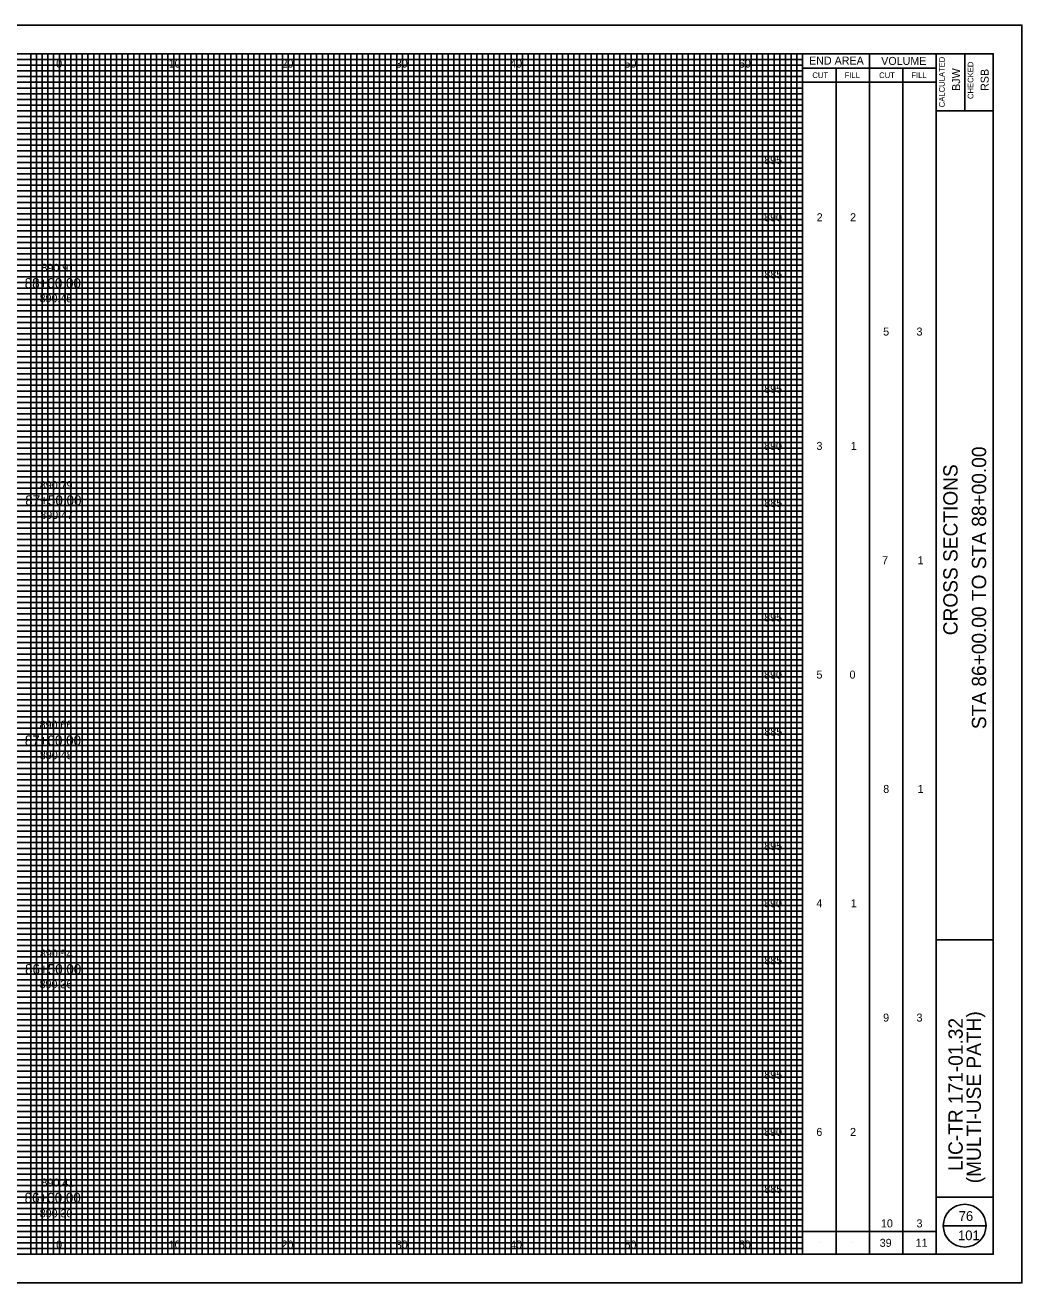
# Model space of a CAD drawing. Extents: x -10 to 160, y -2 to 3672.
# Drawn here: x 72.8 to 160, y 802.5 to 912.5 of the extents above; entities that cross this region are included whole.
import ezdxf

# ---------------------------------------------------------------- set-up
doc = ezdxf.new("R2010")
doc.units = 0
for name, color, linetype in [('SH_Border', 7, 'Continuous'), ('SH_Cut_Line', 7, 'Continuous'), ('SH_Data', 7, 'Continuous'), ('SH_Major_Grid_Line', 7, 'Continuous'), ('SH_Minor_Grid_Line', 7, 'Continuous'), ('SH_Text', 7, 'Continuous'), ('TX_P_10', 7, 'Continuous'), ('TX_X_10', 7, 'Continuous')]:
    doc.layers.add(name, color=color, linetype=linetype)

msp = doc.modelspace()

# ---------------------------------------------------------------- linework, layer by layer
at = {"layer": 'SH_Border'}
for p, q in [((152.5, 805), (152.5, 910)), ((155, 910), (155, 905)), ((152.5, 905), (157.5, 905)), ((152.5, 832.5), (157.5, 832.5)), ((152.5, 810), (157.5, 810))]:
    msp.add_line(p, q, dxfattribs=at)
msp.add_lwpolyline([(0, 910), (157.5, 910), (157.5, 805), (0, 805)], close=True, dxfattribs=at)
at = {"layer": 'SH_Cut_Line'}
msp.add_lwpolyline([(-10, 802.5), (160, 802.5), (160, 912.5), (-10, 912.5)], close=True, dxfattribs=at)
at = {"layer": 'SH_Data'}
for p, q in [((140.83, 805), (140.83, 910)), ((146.67, 805), (146.67, 910)), ((140.83, 908.75), (152.5, 908.75)), ((143.75, 805), (143.75, 908.75)), ((149.58, 805), (149.58, 908.75)), ((140.83, 907.5), (152.5, 907.5)), ((153.12, 807.5), (156.88, 807.5)), ((140.83, 807), (152.5, 807)), ((142.29, 806), (142.29, 806)), ((145.21, 806), (145.21, 806)), ((148.12, 806), (148.12, 806)), ((151.04, 806), (151.04, 806))]:
    msp.add_line(p, q, dxfattribs=at)
msp.add_circle((155, 807.5), 1.87, dxfattribs=at)
at = {"layer": 'SH_Major_Grid_Line'}
for p, q in [((75.83, 805), (75.83, 910)), ((80.83, 805), (80.83, 910)), ((85.83, 805), (85.83, 910)), ((90.83, 805), (90.83, 910)), ((95.83, 805), (95.83, 910)), ((100.83, 805), (100.83, 910)), ((105.83, 805), (105.83, 910)), ((110.83, 805), (110.83, 910)), ((115.83, 805), (115.83, 910)), ((120.83, 805), (120.83, 910)), ((125.83, 805), (125.83, 910)), ((130.83, 805), (130.83, 910)), ((135.83, 805), (135.83, 910)), ((5.83, 905), (140.83, 905)), ((5.83, 900), (140.83, 900)), ((5.83, 895), (140.83, 895)), ((5.83, 890), (140.83, 890)), ((5.83, 885), (140.83, 885)), ((5.83, 880), (140.83, 880)), ((5.83, 875), (140.83, 875)), ((5.83, 870), (140.83, 870)), ((5.83, 865), (140.83, 865)), ((5.83, 860), (140.83, 860)), ((5.83, 855), (140.83, 855)), ((5.83, 850), (140.83, 850)), ((5.83, 845), (140.83, 845)), ((5.83, 840), (140.83, 840)), ((5.83, 835), (140.83, 835)), ((5.83, 830), (140.83, 830)), ((5.83, 825), (140.83, 825)), ((5.83, 820), (140.83, 820)), ((5.83, 815), (140.83, 815)), ((5.83, 810), (140.83, 810))]:
    msp.add_line(p, q, dxfattribs=at)
at = {"layer": 'SH_Minor_Grid_Line'}
for p, q in [((73.33, 805), (73.33, 910)), ((73.83, 805), (73.83, 910)), ((74.33, 805), (74.33, 910)), ((74.83, 805), (74.83, 910)), ((75.33, 805), (75.33, 910)), ((76.33, 805), (76.33, 910)), ((76.83, 805), (76.83, 910)), ((77.33, 805), (77.33, 910)), ((77.83, 805), (77.83, 910)), ((78.33, 805), (78.33, 910)), ((78.83, 805), (78.83, 910)), ((79.33, 805), (79.33, 910)), ((79.83, 805), (79.83, 910)), ((80.33, 805), (80.33, 910)), ((81.33, 805), (81.33, 910)), ((81.83, 805), (81.83, 910)), ((82.33, 805), (82.33, 910)), ((82.83, 805), (82.83, 910)), ((83.33, 805), (83.33, 910)), ((83.83, 805), (83.83, 910)), ((84.33, 805), (84.33, 910)), ((84.83, 805), (84.83, 910)), ((85.33, 805), (85.33, 910)), ((86.33, 805), (86.33, 910)), ((86.83, 805), (86.83, 910)), ((87.33, 805), (87.33, 910)), ((87.83, 805), (87.83, 910)), ((88.33, 805), (88.33, 910)), ((88.83, 805), (88.83, 910)), ((89.33, 805), (89.33, 910)), ((89.83, 805), (89.83, 910)), ((90.33, 805), (90.33, 910)), ((91.33, 805), (91.33, 910)), ((91.83, 805), (91.83, 910)), ((92.33, 805), (92.33, 910)), ((92.83, 805), (92.83, 910)), ((93.33, 805), (93.33, 910)), ((93.83, 805), (93.83, 910)), ((94.33, 805), (94.33, 910)), ((94.83, 805), (94.83, 910)), ((95.33, 805), (95.33, 910)), ((96.33, 805), (96.33, 910)), ((96.83, 805), (96.83, 910)), ((97.33, 805), (97.33, 910)), ((97.83, 805), (97.83, 910)), ((98.33, 805), (98.33, 910)), ((98.83, 805), (98.83, 910)), ((99.33, 805), (99.33, 910)), ((99.83, 805), (99.83, 910)), ((100.33, 805), (100.33, 910)), ((101.33, 805), (101.33, 910)), ((101.83, 805), (101.83, 910)), ((102.33, 805), (102.33, 910)), ((102.83, 805), (102.83, 910)), ((103.33, 805), (103.33, 910)), ((103.83, 805), (103.83, 910)), ((104.33, 805), (104.33, 910)), ((104.83, 805), (104.83, 910)), ((105.33, 805), (105.33, 910)), ((106.33, 805), (106.33, 910)), ((106.83, 805), (106.83, 910)), ((107.33, 805), (107.33, 910)), ((107.83, 805), (107.83, 910)), ((108.33, 805), (108.33, 910)), ((108.83, 805), (108.83, 910)), ((109.33, 805), (109.33, 910)), ((109.83, 805), (109.83, 910)), ((110.33, 805), (110.33, 910)), ((111.33, 805), (111.33, 910)), ((111.83, 805), (111.83, 910)), ((112.33, 805), (112.33, 910)), ((112.83, 805), (112.83, 910)), ((113.33, 805), (113.33, 910)), ((113.83, 805), (113.83, 910)), ((114.33, 805), (114.33, 910)), ((114.83, 805), (114.83, 910)), ((115.33, 805), (115.33, 910)), ((116.33, 805), (116.33, 910)), ((116.83, 805), (116.83, 910)), ((117.33, 805), (117.33, 910)), ((117.83, 805), (117.83, 910)), ((118.33, 805), (118.33, 910)), ((118.83, 805), (118.83, 910)), ((119.33, 805), (119.33, 910)), ((119.83, 805), (119.83, 910)), ((120.33, 805), (120.33, 910)), ((121.33, 805), (121.33, 910)), ((121.83, 805), (121.83, 910)), ((122.33, 805), (122.33, 910)), ((122.83, 805), (122.83, 910)), ((123.33, 805), (123.33, 910)), ((123.83, 805), (123.83, 910)), ((124.33, 805), (124.33, 910)), ((124.83, 805), (124.83, 910)), ((125.33, 805), (125.33, 910)), ((126.33, 805), (126.33, 910)), ((126.83, 805), (126.83, 910)), ((127.33, 805), (127.33, 910)), ((127.83, 805), (127.83, 910)), ((128.33, 805), (128.33, 910)), ((128.83, 805), (128.83, 910)), ((129.33, 805), (129.33, 910)), ((129.83, 805), (129.83, 910)), ((130.33, 805), (130.33, 910)), ((131.33, 805), (131.33, 910)), ((131.83, 805), (131.83, 910)), ((132.33, 805), (132.33, 910)), ((132.83, 805), (132.83, 910)), ((133.33, 805), (133.33, 910)), ((133.83, 805), (133.83, 910)), ((134.33, 805), (134.33, 910)), ((134.83, 805), (134.83, 910)), ((135.33, 805), (135.33, 910)), ((136.33, 805), (136.33, 910)), ((136.83, 805), (136.83, 910)), ((137.33, 805), (137.33, 910)), ((137.83, 805), (137.83, 910)), ((138.33, 805), (138.33, 910)), ((138.83, 805), (138.83, 910)), ((139.33, 805), (139.33, 910)), ((139.83, 805), (139.83, 910)), ((140.33, 805), (140.33, 910)), ((5.83, 909.5), (140.83, 909.5)), ((5.83, 909), (140.83, 909)), ((5.83, 908.5), (140.83, 908.5)), ((5.83, 908), (140.83, 908)), ((5.83, 907.5), (140.83, 907.5)), ((5.83, 907), (140.83, 907)), ((5.83, 906.5), (140.83, 906.5)), ((5.83, 906), (140.83, 906)), ((5.83, 905.5), (140.83, 905.5)), ((5.83, 904.5), (140.83, 904.5)), ((5.83, 904), (140.83, 904)), ((5.83, 903.5), (140.83, 903.5)), ((5.83, 903), (140.83, 903)), ((5.83, 902.5), (140.83, 902.5)), ((5.83, 902), (140.83, 902)), ((5.83, 901.5), (140.83, 901.5)), ((5.83, 901), (140.83, 901)), ((5.83, 900.5), (140.83, 900.5)), ((5.83, 899.5), (140.83, 899.5)), ((5.83, 899), (140.83, 899)), ((5.83, 898.5), (140.83, 898.5)), ((5.83, 898), (140.83, 898)), ((5.83, 897.5), (140.83, 897.5)), ((5.83, 897), (140.83, 897)), ((5.83, 896.5), (140.83, 896.5)), ((5.83, 896), (140.83, 896)), ((5.83, 895.5), (140.83, 895.5)), ((5.83, 894.5), (140.83, 894.5)), ((5.83, 894), (140.83, 894)), ((5.83, 893.5), (140.83, 893.5)), ((5.83, 893), (140.83, 893)), ((5.83, 892.5), (140.83, 892.5)), ((5.83, 892), (140.83, 892)), ((5.83, 891.5), (140.83, 891.5)), ((5.83, 891), (140.83, 891)), ((5.83, 890.5), (140.83, 890.5)), ((5.83, 889.5), (140.83, 889.5)), ((5.83, 889), (140.83, 889)), ((5.83, 888.5), (140.83, 888.5)), ((5.83, 888), (140.83, 888)), ((5.83, 887.5), (140.83, 887.5)), ((5.83, 887), (140.83, 887)), ((5.83, 886.5), (140.83, 886.5)), ((5.83, 886), (140.83, 886)), ((5.83, 885.5), (140.83, 885.5)), ((5.83, 884.5), (140.83, 884.5)), ((5.83, 884), (140.83, 884)), ((5.83, 883.5), (140.83, 883.5)), ((5.83, 883), (140.83, 883)), ((5.83, 882.5), (140.83, 882.5)), ((5.83, 882), (140.83, 882)), ((5.83, 881.5), (140.83, 881.5)), ((5.83, 881), (140.83, 881)), ((5.83, 880.5), (140.83, 880.5)), ((5.83, 879.5), (140.83, 879.5)), ((5.83, 879), (140.83, 879)), ((5.83, 878.5), (140.83, 878.5)), ((5.83, 878), (140.83, 878)), ((5.83, 877.5), (140.83, 877.5)), ((5.83, 877), (140.83, 877)), ((5.83, 876.5), (140.83, 876.5)), ((5.83, 876), (140.83, 876)), ((5.83, 875.5), (140.83, 875.5)), ((5.83, 874.5), (140.83, 874.5)), ((5.83, 874), (140.83, 874)), ((5.83, 873.5), (140.83, 873.5)), ((5.83, 873), (140.83, 873)), ((5.83, 872.5), (140.83, 872.5)), ((5.83, 872), (140.83, 872)), ((5.83, 871.5), (140.83, 871.5)), ((5.83, 871), (140.83, 871)), ((5.83, 870.5), (140.83, 870.5)), ((5.83, 869.5), (140.83, 869.5)), ((5.83, 869), (140.83, 869)), ((5.83, 868.5), (140.83, 868.5)), ((5.83, 868), (140.83, 868)), ((5.83, 867.5), (140.83, 867.5)), ((5.83, 867), (140.83, 867)), ((5.83, 866.5), (140.83, 866.5)), ((5.83, 866), (140.83, 866)), ((5.83, 865.5), (140.83, 865.5)), ((5.83, 864.5), (140.83, 864.5)), ((5.83, 864), (140.83, 864)), ((5.83, 863.5), (140.83, 863.5)), ((5.83, 863), (140.83, 863)), ((5.83, 862.5), (140.83, 862.5)), ((5.83, 862), (140.83, 862)), ((5.83, 861.5), (140.83, 861.5)), ((5.83, 861), (140.83, 861)), ((5.83, 860.5), (140.83, 860.5)), ((5.83, 859.5), (140.83, 859.5)), ((5.83, 859), (140.83, 859)), ((5.83, 858.5), (140.83, 858.5)), ((5.83, 858), (140.83, 858)), ((5.83, 857.5), (140.83, 857.5)), ((5.83, 857), (140.83, 857)), ((5.83, 856.5), (140.83, 856.5)), ((5.83, 856), (140.83, 856)), ((5.83, 855.5), (140.83, 855.5)), ((5.83, 854.5), (140.83, 854.5)), ((5.83, 854), (140.83, 854)), ((5.83, 853.5), (140.83, 853.5)), ((5.83, 853), (140.83, 853)), ((5.83, 852.5), (140.83, 852.5)), ((5.83, 852), (140.83, 852)), ((5.83, 851.5), (140.83, 851.5)), ((5.83, 851), (140.83, 851)), ((5.83, 850.5), (140.83, 850.5)), ((5.83, 849.5), (140.83, 849.5)), ((5.83, 849), (140.83, 849)), ((5.83, 848.5), (140.83, 848.5)), ((5.83, 848), (140.83, 848)), ((5.83, 847.5), (140.83, 847.5)), ((5.83, 847), (140.83, 847)), ((5.83, 846.5), (140.83, 846.5)), ((5.83, 846), (140.83, 846)), ((5.83, 845.5), (140.83, 845.5)), ((5.83, 844.5), (140.83, 844.5)), ((5.83, 844), (140.83, 844)), ((5.83, 843.5), (140.83, 843.5)), ((5.83, 843), (140.83, 843)), ((5.83, 842.5), (140.83, 842.5)), ((5.83, 842), (140.83, 842)), ((5.83, 841.5), (140.83, 841.5)), ((5.83, 841), (140.83, 841)), ((5.83, 840.5), (140.83, 840.5)), ((5.83, 839.5), (140.83, 839.5)), ((5.83, 839), (140.83, 839)), ((5.83, 838.5), (140.83, 838.5)), ((5.83, 838), (140.83, 838)), ((5.83, 837.5), (140.83, 837.5)), ((5.83, 837), (140.83, 837)), ((5.83, 836.5), (140.83, 836.5)), ((5.83, 836), (140.83, 836)), ((5.83, 835.5), (140.83, 835.5)), ((5.83, 834.5), (140.83, 834.5)), ((5.83, 834), (140.83, 834)), ((5.83, 833.5), (140.83, 833.5)), ((5.83, 833), (140.83, 833)), ((5.83, 832.5), (140.83, 832.5)), ((5.83, 832), (140.83, 832)), ((5.83, 831.5), (140.83, 831.5)), ((5.83, 831), (140.83, 831)), ((5.83, 830.5), (140.83, 830.5)), ((5.83, 829.5), (140.83, 829.5)), ((5.83, 829), (140.83, 829)), ((5.83, 828.5), (140.83, 828.5)), ((5.83, 828), (140.83, 828)), ((5.83, 827.5), (140.83, 827.5)), ((5.83, 827), (140.83, 827)), ((5.83, 826.5), (140.83, 826.5)), ((5.83, 826), (140.83, 826)), ((5.83, 825.5), (140.83, 825.5)), ((5.83, 824.5), (140.83, 824.5)), ((5.83, 824), (140.83, 824)), ((5.83, 823.5), (140.83, 823.5)), ((5.83, 823), (140.83, 823)), ((5.83, 822.5), (140.83, 822.5)), ((5.83, 822), (140.83, 822)), ((5.83, 821.5), (140.83, 821.5)), ((5.83, 821), (140.83, 821)), ((5.83, 820.5), (140.83, 820.5)), ((5.83, 819.5), (140.83, 819.5)), ((5.83, 819), (140.83, 819)), ((5.83, 818.5), (140.83, 818.5)), ((5.83, 818), (140.83, 818)), ((5.83, 817.5), (140.83, 817.5)), ((5.83, 817), (140.83, 817)), ((5.83, 816.5), (140.83, 816.5)), ((5.83, 816), (140.83, 816)), ((5.83, 815.5), (140.83, 815.5)), ((5.83, 814.5), (140.83, 814.5)), ((5.83, 814), (140.83, 814)), ((5.83, 813.5), (140.83, 813.5)), ((5.83, 813), (140.83, 813)), ((5.83, 812.5), (140.83, 812.5)), ((5.83, 812), (140.83, 812)), ((5.83, 811.5), (140.83, 811.5)), ((5.83, 811), (140.83, 811)), ((5.83, 810.5), (140.83, 810.5)), ((5.83, 809.5), (140.83, 809.5)), ((5.83, 809), (140.83, 809)), ((5.83, 808.5), (140.83, 808.5)), ((5.83, 808), (140.83, 808)), ((5.83, 807.5), (140.83, 807.5)), ((5.83, 807), (140.83, 807)), ((5.83, 806.5), (140.83, 806.5)), ((5.83, 806), (140.83, 806)), ((5.83, 805.5), (140.83, 805.5))]:
    msp.add_line(p, q, dxfattribs=at)

# ---------------------------------------------------------------- texts
at = {"layer": 'SH_Data'}
for s, height, p in [('END AREA', 0.7, (141.39, 909.05)), ('VOLUME', 0.7, (147.7, 909.02)), ('CUT', 0.5, (141.68, 907.87)), ('FILL', 0.5, (144.5, 907.87)), ('CUT', 0.5, (147.52, 907.87)), ('FILL', 0.5, (150.34, 907.87)), ('76', 0.85, (154.48, 807.92)), ('101', 0.85, (154.42, 806.23))]:
    msp.add_text(s, height=height, dxfattribs=at).set_placement(p)
for s, height, p in [('CALCULATED', 0.5, (153.26, 905.32)), ('BJW', 0.7, (154.6, 906.75)), ('CHECKED', 0.5, (155.76, 906.04)), ('RSB', 0.7, (157.1, 906.75)), ('STA 86+00.00 TO STA 88+00.00', 1.25, (156.88, 850.93)), ('CROSS SECTIONS', 1.25, (154.38, 859.14)), ('(MULTI-USE PATH)', 1.25, (156.42, 811.21)), ('LIC-TR 171-01.32', 1.25, (154.83, 812.29))]:
    msp.add_text(s, height=height, rotation=90, dxfattribs=at).set_placement(p)
at = {"layer": 'SH_Text'}
for s, height, p in [('0', 0.7, (75.55, 908.79)), ('10', 0.7, (85.39, 908.79)), ('20', 0.7, (95.26, 908.79)), ('30', 0.7, (105.25, 908.79)), ('40', 0.7, (115.25, 908.79)), ('50', 0.7, (125.25, 908.79)), ('60', 0.7, (135.25, 908.79)), ('895', 0.7, (137.47, 900.35)), ('890', 0.7, (137.46, 895.35)), ('2', 0.7, (142.06, 895.35)), ('2', 0.7, (144.98, 895.35)), ('885', 0.7, (137.48, 890.35)), ('88+00.00', 0.875, (72.8, 889.5)), ('5', 0.7, (147.87, 885.35)), ('3', 0.7, (150.79, 885.35)), ('895', 0.7, (137.47, 880.35)), ('890', 0.7, (137.46, 875.35)), ('3', 0.7, (142.04, 875.35)), ('1', 0.7, (145.04, 875.35)), ('87+50.00', 0.875, (72.85, 870.5)), ('885', 0.7, (137.48, 870.35)), ('7', 0.7, (147.78, 865.35)), ('1', 0.7, (150.88, 865.35)), ('895', 0.7, (137.47, 860.35)), ('890', 0.7, (137.46, 855.35)), ('5', 0.7, (142.04, 855.35)), ('0', 0.7, (144.93, 855.35)), ('87+00.00', 0.875, (72.81, 849.5)), ('885', 0.7, (137.48, 850.35)), ('8', 0.7, (147.88, 845.35)), ('1', 0.7, (150.88, 845.35)), ('895', 0.7, (137.47, 840.35)), ('890', 0.7, (137.46, 835.35)), ('4', 0.7, (142.03, 835.35)), ('1', 0.7, (145.04, 835.35)), ('885', 0.7, (137.48, 830.35)), ('86+50.00', 0.875, (72.83, 829.5)), ('9', 0.7, (147.87, 825.35)), ('3', 0.7, (150.79, 825.35)), ('895', 0.7, (137.47, 820.35)), ('890', 0.7, (137.46, 815.35)), ('6', 0.7, (142.03, 815.35)), ('2', 0.7, (144.98, 815.35)), ('885', 0.7, (137.48, 810.35)), ('86+00.00', 0.875, (72.79, 809.5)), ('10', 0.7, (147.68, 807.35)), ('3', 0.7, (150.79, 807.35)), ('39', 0.7, (147.57, 805.65)), ('11', 0.7, (150.71, 805.65)), ('0', 0.7, (75.55, 805.5)), ('10', 0.7, (85.39, 805.5)), ('20', 0.7, (95.26, 805.5)), ('30', 0.7, (105.25, 805.5)), ('40', 0.7, (115.25, 805.5)), ('50', 0.7, (125.25, 805.5)), ('60', 0.7, (135.25, 805.5))]:
    msp.add_text(s, height=height, dxfattribs=at).set_placement(p)
at = {"layer": 'TX_P_10'}
for s, p in [('890.91', (74.26, 890.93)), ('890.79', (74.12, 871.92)), ('890.66', (74.1, 850.97)), ('890.54', (74.13, 830.95)), ('890.41', (74.26, 810.92))]:
    msp.add_text(s, height=0.7, dxfattribs=at).set_placement(p)
at = {"layer": 'TX_X_10'}
for s, p in [('890.45', (74.1, 888.26)), ('890.47', (74.16, 869.31)), ('890.48', (74.12, 848.3)), ('890.36', (74.1, 828.27)), ('890.30', (74.11, 808.23))]:
    msp.add_text(s, height=0.7, dxfattribs=at).set_placement(p)

doc.saveas('drawing.dxf')
